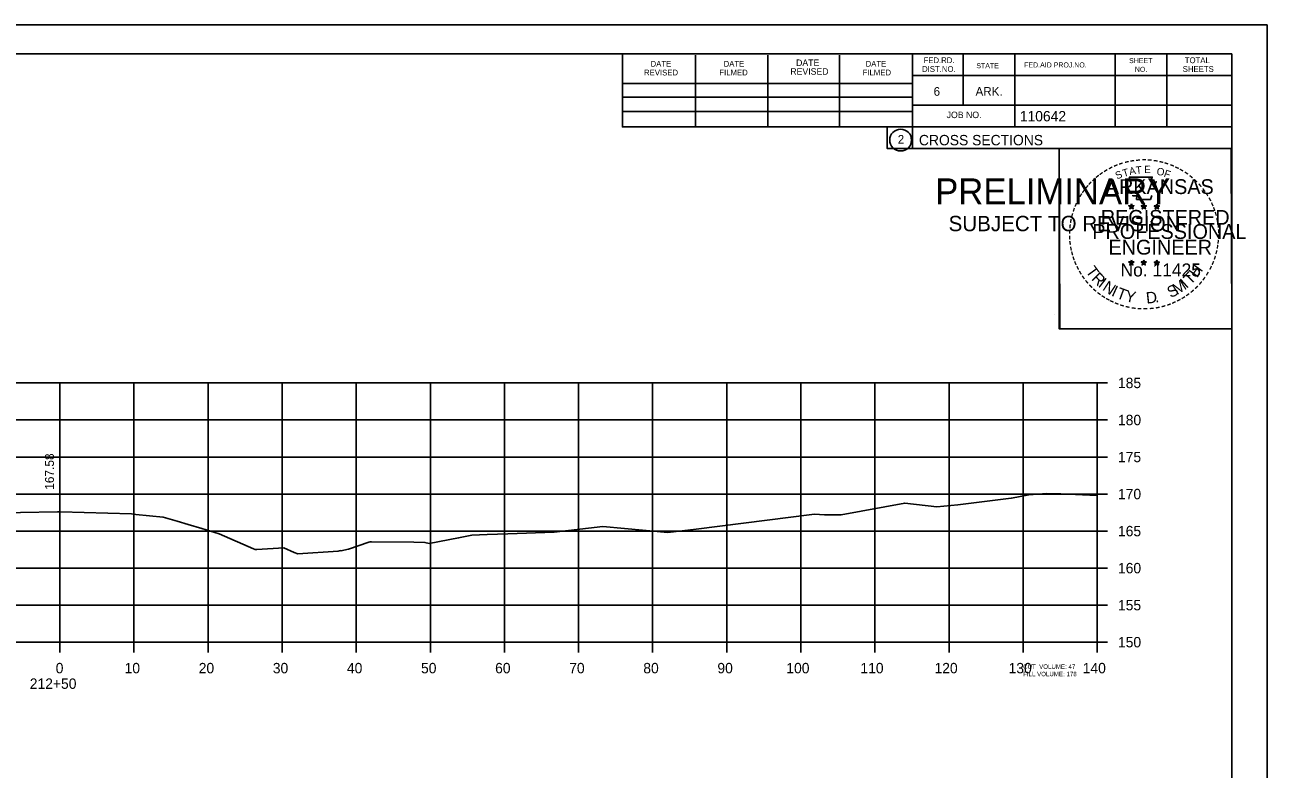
# Model space of a CAD drawing. Extents: x 1368503 to 1373085, y 379840 to 381833.
# Drawn here: x 1368668.3 to 1368836, y 381092.2 to 381192.7 of the extents above; entities that cross this region are included whole.
import ezdxf

# ---------------------------------------------------------------- set-up
doc = ezdxf.new("R2010")
doc.units = 0
for name, color, linetype in [('S_BRIDGE', 7, 'Continuous'), ('S_EDGE_PAVEMENT', 7, 'Continuous'), ('S_LANDSCAPING', 7, 'Continuous'), ('S_MISC_BOUNDARY', 7, 'Continuous'), ('S_MISC_BOUNDARY_ANNOT', 7, 'Continuous'), ('S_PHOTO_CENTERS', 7, 'Continuous'), ('S_PHOTO_NOTES', 7, 'Continuous'), ('S_TRAILS', 7, 'Continuous'), ('S_TRAILS_ANNOT', 7, 'Continuous')]:
    doc.layers.add(name, color=color, linetype=linetype)

msp = doc.modelspace()

# ---------------------------------------------------------------- linework, layer by layer
at = {"layer": 'S_BRIDGE'}
for p, q in [((1368515.06, 381188.84), (1368831.24, 381188.84)), ((1368748.98, 381178.96), (1368748.98, 381188.84)), ((1368758.84, 381178.96), (1368758.84, 381188.64)), ((1368768.6, 381178.96), (1368768.6, 381188.64)), ((1368778.28, 381178.96), (1368778.28, 381188.64)), ((1368788.14, 381188.84), (1368788.14, 381176.04)), ((1368794.98, 381188.84), (1368794.98, 381181.9)), ((1368801.92, 381188.84), (1368801.92, 381178.96)), ((1368815.5, 381188.84), (1368815.5, 381178.96)), ((1368822.44, 381188.84), (1368822.44, 381178.96)), ((1368831.24, 380983.38), (1368831.24, 381188.84)), ((1368748.98, 381184.82), (1368788.14, 381184.82)), ((1368831.24, 381185.9), (1368788.14, 381185.9)), ((1368831.24, 381185.92), (1368831.24, 381185.92)), ((1368748.98, 381182.96), (1368788.14, 381182.96)), ((1368831.24, 381181.9), (1368788.14, 381181.9)), ((1368791.1, 381181.9), (1368831.24, 381181.9)), ((1368748.98, 381178.96), (1368748.98, 381181.02)), ((1368748.98, 381181.02), (1368788.14, 381181.02)), ((1368831.24, 381178.96), (1368748.98, 381178.96)), ((1368788.14, 381176.04), (1368831.24, 381176.04))]:
    msp.add_line(p, q, dxfattribs=at)
msp.add_circle((1368786.53, 381177.18), 1.47, dxfattribs=at)
at = {"layer": 'S_EDGE_PAVEMENT'}
for p, q in [((1368813.06, 381109.38), (1368813.06, 381144.38)), ((1368814.46, 381144.38), (1368813.06, 381144.38)), ((1368814.46, 381139.38), (1368813.06, 381139.38)), ((1368814.46, 381134.38), (1368813.06, 381134.38)), ((1368814.46, 381129.38), (1368813.06, 381129.38)), ((1368814.46, 381124.38), (1368813.06, 381124.38)), ((1368814.46, 381119.38), (1368813.06, 381119.38)), ((1368814.46, 381114.38), (1368813.06, 381114.38)), ((1368533.06, 381109.38), (1368813.06, 381109.38)), ((1368673.06, 381107.98), (1368673.06, 381109.38)), ((1368683.06, 381107.98), (1368683.06, 381109.38)), ((1368693.06, 381107.98), (1368693.06, 381109.38)), ((1368703.06, 381107.98), (1368703.06, 381109.38)), ((1368713.06, 381107.98), (1368713.06, 381109.38)), ((1368723.06, 381107.98), (1368723.06, 381109.38)), ((1368733.06, 381107.98), (1368733.06, 381109.38)), ((1368743.06, 381107.98), (1368743.06, 381109.38)), ((1368753.06, 381107.98), (1368753.06, 381109.38)), ((1368763.06, 381107.98), (1368763.06, 381109.38)), ((1368773.06, 381107.98), (1368773.06, 381109.38)), ((1368783.06, 381107.98), (1368783.06, 381109.38)), ((1368793.06, 381107.98), (1368793.06, 381109.38)), ((1368803.06, 381107.98), (1368803.06, 381109.38)), ((1368813.06, 381107.98), (1368813.06, 381109.38)), ((1368814.46, 381109.38), (1368813.06, 381109.38))]:
    msp.add_line(p, q, dxfattribs=at)
at = {"layer": 'S_LANDSCAPING'}
for p, q in [((1368817.32, 381168.3), (1368817.67, 381168.18)), ((1368817.32, 381168.3), (1368817.58, 381168.25)), ((1368817.32, 381168.3), (1368817.56, 381168.17)), ((1368817.46, 381167.89), (1368817.67, 381168.18)), ((1368817.46, 381167.89), (1368817.58, 381168.13)), ((1368817.46, 381167.89), (1368817.67, 381168.1)), ((1368817.67, 381168.55), (1368817.63, 381168.3)), ((1368817.67, 381168.18), (1368817.67, 381168.55)), ((1368817.67, 381168.55), (1368817.72, 381168.3)), ((1368818.02, 381168.3), (1368817.67, 381168.18)), ((1368817.89, 381167.89), (1368817.67, 381168.18)), ((1368817.89, 381167.89), (1368817.67, 381168.1)), ((1368818.02, 381168.3), (1368817.73, 381168.25)), ((1368817.89, 381167.89), (1368817.75, 381168.18)), ((1368818.02, 381168.3), (1368817.82, 381168.19)), ((1368818.99, 381168.3), (1368819.34, 381168.18)), ((1368818.99, 381168.3), (1368819.25, 381168.25)), ((1368818.99, 381168.3), (1368819.23, 381168.17)), ((1368819.13, 381167.89), (1368819.34, 381168.18)), ((1368819.13, 381167.89), (1368819.25, 381168.13)), ((1368819.13, 381167.89), (1368819.34, 381168.1)), ((1368819.34, 381168.55), (1368819.3, 381168.3)), ((1368819.34, 381168.18), (1368819.34, 381168.55)), ((1368819.34, 381168.55), (1368819.39, 381168.3)), ((1368819.69, 381168.3), (1368819.34, 381168.18)), ((1368819.56, 381167.89), (1368819.34, 381168.18)), ((1368819.56, 381167.89), (1368819.34, 381168.1)), ((1368819.69, 381168.3), (1368819.4, 381168.25)), ((1368819.56, 381167.89), (1368819.42, 381168.18)), ((1368819.69, 381168.3), (1368819.49, 381168.19)), ((1368820.76, 381168.28), (1368821.11, 381168.17)), ((1368820.76, 381168.28), (1368821.01, 381168.24)), ((1368820.76, 381168.28), (1368820.99, 381168.16)), ((1368820.89, 381167.88), (1368821.11, 381168.17)), ((1368820.89, 381167.88), (1368821.02, 381168.12)), ((1368820.89, 381167.88), (1368821.1, 381168.09)), ((1368821.11, 381168.54), (1368821.07, 381168.29)), ((1368821.32, 381167.88), (1368821.1, 381168.09)), ((1368821.11, 381168.17), (1368821.11, 381168.54)), ((1368821.11, 381168.54), (1368821.16, 381168.29)), ((1368821.45, 381168.28), (1368821.11, 381168.17)), ((1368821.32, 381167.88), (1368821.11, 381168.17)), ((1368821.45, 381168.28), (1368821.17, 381168.23)), ((1368821.32, 381167.88), (1368821.18, 381168.17)), ((1368821.45, 381168.28), (1368821.25, 381168.18)), ((1368817.32, 381160.72), (1368817.67, 381160.61)), ((1368817.32, 381160.72), (1368817.57, 381160.68)), ((1368817.32, 381160.72), (1368817.56, 381160.6)), ((1368817.45, 381160.31), (1368817.67, 381160.61)), ((1368817.45, 381160.31), (1368817.58, 381160.56)), ((1368817.45, 381160.31), (1368817.67, 381160.53)), ((1368817.67, 381160.98), (1368817.63, 381160.72)), ((1368817.67, 381160.61), (1368817.67, 381160.98)), ((1368817.67, 381160.98), (1368817.72, 381160.73)), ((1368818.02, 381160.72), (1368817.67, 381160.61)), ((1368817.88, 381160.31), (1368817.67, 381160.61)), ((1368817.88, 381160.31), (1368817.67, 381160.53)), ((1368818.02, 381160.72), (1368817.73, 381160.67)), ((1368817.88, 381160.31), (1368817.74, 381160.61)), ((1368818.02, 381160.72), (1368817.81, 381160.62)), ((1368818.99, 381160.72), (1368819.34, 381160.61)), ((1368818.99, 381160.72), (1368819.24, 381160.68)), ((1368818.99, 381160.72), (1368819.23, 381160.6)), ((1368819.12, 381160.31), (1368819.34, 381160.61)), ((1368819.12, 381160.31), (1368819.25, 381160.56)), ((1368819.12, 381160.31), (1368819.34, 381160.53)), ((1368819.34, 381160.98), (1368819.3, 381160.72)), ((1368819.34, 381160.61), (1368819.34, 381160.98)), ((1368819.34, 381160.98), (1368819.39, 381160.73)), ((1368819.68, 381160.72), (1368819.34, 381160.61)), ((1368819.55, 381160.31), (1368819.34, 381160.61)), ((1368819.55, 381160.31), (1368819.34, 381160.53)), ((1368819.68, 381160.72), (1368819.4, 381160.67)), ((1368819.55, 381160.31), (1368819.41, 381160.61)), ((1368819.68, 381160.72), (1368819.48, 381160.62)), ((1368820.76, 381160.71), (1368821.1, 381160.6)), ((1368820.76, 381160.71), (1368821.01, 381160.67)), ((1368820.76, 381160.71), (1368820.99, 381160.59)), ((1368820.89, 381160.3), (1368821.1, 381160.6)), ((1368820.89, 381160.3), (1368821.01, 381160.55)), ((1368820.89, 381160.3), (1368821.1, 381160.52)), ((1368821.1, 381160.97), (1368821.06, 381160.71)), ((1368821.1, 381160.6), (1368821.1, 381160.97)), ((1368821.1, 381160.97), (1368821.15, 381160.72)), ((1368821.45, 381160.71), (1368821.1, 381160.6)), ((1368821.32, 381160.3), (1368821.1, 381160.6)), ((1368821.32, 381160.3), (1368821.1, 381160.52)), ((1368821.45, 381160.71), (1368821.17, 381160.66)), ((1368821.32, 381160.3), (1368821.18, 381160.6)), ((1368821.45, 381160.71), (1368821.25, 381160.61))]:
    msp.add_line(p, q, dxfattribs=at)
for points in [[(1368817.36, 381172.17), (1368817.63, 381171.35)], [(1368820.88, 381171.25), (1368821.02, 381171.54), (1368820.33, 381171.51), (1368820.48, 381172.17), (1368817.36, 381172.17)], [(1368817.86, 381169.75), (1368817.86, 381169.66), (1368818.42, 381169.64), (1368818.37, 381169.17), (1368820.24, 381169.17), (1368820.44, 381169.71)], [(1368817.67, 381168.55), (1368817.89, 381167.89), (1368817.32, 381168.3), (1368818.02, 381168.3), (1368817.46, 381167.89), (1368817.67, 381168.55)], [(1368819.34, 381168.55), (1368819.56, 381167.89), (1368818.99, 381168.3), (1368819.69, 381168.3), (1368819.13, 381167.89), (1368819.34, 381168.55)], [(1368821.11, 381168.54), (1368821.32, 381167.88), (1368820.76, 381168.28), (1368821.45, 381168.28), (1368820.89, 381167.88), (1368821.11, 381168.54)], [(1368817.67, 381160.98), (1368817.88, 381160.31), (1368817.32, 381160.72), (1368818.02, 381160.72), (1368817.45, 381160.31), (1368817.67, 381160.98)], [(1368819.34, 381160.98), (1368819.55, 381160.31), (1368818.99, 381160.72), (1368819.68, 381160.72), (1368819.12, 381160.31), (1368819.34, 381160.98)], [(1368821.1, 381160.97), (1368821.32, 381160.3), (1368820.76, 381160.71), (1368821.45, 381160.71), (1368820.89, 381160.3), (1368821.1, 381160.97)]]:
    msp.add_lwpolyline(points, dxfattribs=at)
for centre, radius in [((1368817.67, 381168.18), 0.172), ((1368817.67, 381168.18), 0.145), ((1368817.67, 381168.18), 0.116), ((1368817.67, 381168.18), 0.0991), ((1368817.67, 381168.18), 0.0747), ((1368817.67, 381168.18), 0.0495), ((1368817.67, 381168.18), 0.0296), ((1368819.34, 381168.18), 0.172), ((1368819.34, 381168.18), 0.145), ((1368819.34, 381168.18), 0.116), ((1368819.34, 381168.18), 0.0991), ((1368819.34, 381168.18), 0.0747), ((1368819.34, 381168.18), 0.0495), ((1368819.34, 381168.18), 0.0296), ((1368821.11, 381168.17), 0.172), ((1368821.11, 381168.17), 0.145), ((1368821.11, 381168.17), 0.116), ((1368821.11, 381168.17), 0.0991), ((1368821.11, 381168.17), 0.0747), ((1368821.11, 381168.17), 0.0495), ((1368821.11, 381168.17), 0.0296), ((1368817.67, 381160.61), 0.172), ((1368817.67, 381160.61), 0.145), ((1368817.67, 381160.61), 0.116), ((1368817.67, 381160.61), 0.0991), ((1368817.67, 381160.61), 0.0747), ((1368817.67, 381160.61), 0.0495), ((1368817.67, 381160.61), 0.0296), ((1368819.34, 381160.61), 0.172), ((1368819.34, 381160.61), 0.145), ((1368819.34, 381160.61), 0.116), ((1368819.34, 381160.61), 0.0991), ((1368819.34, 381160.61), 0.0747), ((1368819.34, 381160.61), 0.0495), ((1368819.34, 381160.61), 0.0296), ((1368821.1, 381160.6), 0.172), ((1368821.1, 381160.6), 0.145), ((1368821.1, 381160.6), 0.116), ((1368821.1, 381160.6), 0.0991), ((1368821.1, 381160.6), 0.0747), ((1368821.1, 381160.6), 0.0495), ((1368821.1, 381160.6), 0.0296)]:
    msp.add_circle(centre, radius, dxfattribs=at)
at = {"layer": 'S_MISC_BOUNDARY'}
msp.add_lwpolyline([(1368662.7, 381126.81), (1368672.76, 381126.97), (1368673.15, 381126.96), (1368682.74, 381126.69), (1368683.3, 381126.64), (1368687.02, 381126.27), (1368688.9, 381125.7), (1368690.37, 381125.28), (1368692.2, 381124.71), (1368694.56, 381124.01), (1368699.2, 381121.97), (1368699.4, 381121.88), (1368699.66, 381121.89), (1368703.29, 381122.12), (1368704.7, 381121.49), (1368705.19, 381121.29), (1368710.6, 381121.67), (1368710.93, 381121.74), (1368710.99, 381121.7), (1368712.03, 381121.95), (1368714.76, 381122.87), (1368714.93, 381122.93), (1368714.97, 381122.93), (1368715.1, 381122.93), (1368720.82, 381122.89), (1368722.33, 381122.85), (1368722.92, 381122.71), (1368726.88, 381123.45), (1368728.67, 381123.84), (1368730.71, 381123.93), (1368733.5, 381124.02), (1368739.78, 381124.25), (1368746.36, 381125.01), (1368755.09, 381124.18), (1368758.92, 381124.66), (1368774.92, 381126.68), (1368776.26, 381126.59), (1368777, 381126.56), (1368778.48, 381126.57), (1368787.08, 381128.16), (1368791.41, 381127.65), (1368794.23, 381127.93), (1368801.45, 381128.82), (1368801.48, 381128.82), (1368803.82, 381129.26), (1368806.25, 381129.44), (1368808.14, 381129.4), (1368813.06, 381129.18)], dxfattribs=at)
at = {"layer": 'S_PHOTO_CENTERS'}
for p, q in [((1368533.06, 381144.38), (1368813.06, 381144.38)), ((1368673.06, 381109.38), (1368673.06, 381144.38)), ((1368683.06, 381109.38), (1368683.06, 381144.38)), ((1368693.06, 381109.38), (1368693.06, 381144.38)), ((1368703.06, 381109.38), (1368703.06, 381144.38)), ((1368713.06, 381109.38), (1368713.06, 381144.38)), ((1368723.06, 381109.38), (1368723.06, 381144.38)), ((1368733.06, 381109.38), (1368733.06, 381144.38)), ((1368743.06, 381109.38), (1368743.06, 381144.38)), ((1368753.06, 381109.38), (1368753.06, 381144.38)), ((1368763.06, 381109.38), (1368763.06, 381144.38)), ((1368773.06, 381109.38), (1368773.06, 381144.38)), ((1368783.06, 381109.38), (1368783.06, 381144.38)), ((1368793.06, 381109.38), (1368793.06, 381144.38)), ((1368803.06, 381109.38), (1368803.06, 381144.38)), ((1368813.06, 381109.38), (1368813.06, 381144.38)), ((1368533.06, 381139.38), (1368813.06, 381139.38)), ((1368533.06, 381134.38), (1368813.06, 381134.38)), ((1368533.06, 381129.38), (1368813.06, 381129.38)), ((1368533.06, 381124.38), (1368813.06, 381124.38)), ((1368533.06, 381119.38), (1368813.06, 381119.38)), ((1368533.06, 381114.38), (1368813.06, 381114.38)), ((1368533.06, 381109.38), (1368813.06, 381109.38))]:
    msp.add_line(p, q, dxfattribs=at)
at = {"layer": 'S_PHOTO_NOTES'}
for p, q in [((1368502.66, 381192.73), (1368835.99, 381192.73)), ((1368807.27, 381153.58), (1368807.27, 381153.58))]:
    msp.add_line(p, q, dxfattribs=at)
for points in [[(1368502.65, 381192.73), (1368835.99, 381192.73), (1368835.99, 380979.4), (1368502.65, 380979.4)], [(1368748.98, 381188.84), (1368748.98, 381178.96), (1368784.71, 381178.96), (1368784.71, 381176.04), (1368807.91, 381176.04), (1368807.91, 381151.71), (1368831.24, 381151.71), (1368831.24, 380983.38), (1368515.06, 380983.38), (1368515.06, 381188.84)], [(1368807.91, 381176.04), (1368831.12, 381176.04), (1368831.24, 381151.71), (1368808.03, 381151.71)]]:
    msp.add_lwpolyline(points, close=True, dxfattribs=at)

# ---------------------------------------------------------------- texts
at = {"layer": 'S_BRIDGE'}
for s, height, p in [('DATE', 0.879, (1368772.42, 381187.18)), ('FED.RD.', 0.782, (1368789.62, 381187.56)), ('SHEET', 0.684, (1368817.36, 381187.56)), ('TOTAL', 0.782, (1368824.88, 381187.56)), ('REVISED', 0.782, (1368751.9, 381185.9)), ('DATE', 0.782, (1368752.78, 381187.08)), ('FILMED', 0.782, (1368762.06, 381185.9)), ('DATE', 0.782, (1368762.64, 381187.08)), ('REVISED', 0.879, (1368771.64, 381186)), ('FILMED', 0.782, (1368781.4, 381185.9)), ('DATE', 0.782, (1368781.8, 381187.08)), ('DIST.NO.', 0.782, (1368789.42, 381186.38)), ('STATE', 0.684, (1368796.74, 381186.88)), ('FED.AID PROJ.NO.', 0.684, (1368803.2, 381186.98)), ('NO.', 0.684, (1368818.14, 381186.38)), ('SHEETS', 0.782, (1368824.6, 381186.38)), ('6', 1.17, (1368790.98, 381183.16)), ('ARK.', 1.172, (1368796.64, 381183.16)), ('JOB NO.', 0.879, (1368792.74, 381180.14)), ('110642', 1.4, (1368802.61, 381179.7)), ('2', 1.17, (1368786.14, 381176.69)), ('CROSS SECTIONS', 1.4, (1368789, 381176.47))]:
    msp.add_text(s, height=height, rotation=360, dxfattribs=at).set_placement(p)
at = {"layer": 'S_LANDSCAPING'}
for s, height, rotation, p in [('-', 1.6, 5.8968, (1368818.27, 381173.81)), ('-', 1.6, 0.1862, (1368819.04, 381173.89)), ('-', 1.6, 357.743, (1368819.76, 381173.87)), ('-', 1.6, 36.2317, (1368813.67, 381171.95)), ('-', 1.6, 34.0636, (1368814.25, 381172.34)), ('-', 1.6, 28.7918, (1368814.85, 381172.71)), ('-', 1.6, 24.3072, (1368815.48, 381173.03)), ('S', 1, 21.594, (1368815.72, 381171.85)), ('-', 1.6, 19.1761, (1368816.11, 381173.3)), ('T', 1, 16.4036, (1368816.63, 381172.18)), ('-', 1.6, 13.6301, (1368816.86, 381173.54)), ('A', 1, 11.2132, (1368817.46, 381172.43)), ('-', 1.6, 10.2193, (1368817.54, 381173.7)), ('T', 1, 6.0228, (1368818.31, 381172.6)), ('E', 1, 0.8323, (1368819.41, 381172.71)), ('-', 1.6, 352.1617, (1368820.51, 381173.82)), ('O', 1, 350.4515, (1368821.02, 381172.5)), ('-', 1.6, 347.2049, (1368821.23, 381173.7)), ('F', 1, 340.0707, (1368821.97, 381172.27)), ('-', 1.6, 342.3362, (1368821.86, 381173.55)), ('-', 1.6, 337.8551, (1368822.6, 381173.32)), ('-', 1.6, 334.1211, (1368823.23, 381173.05)), ('-', 1.6, 329.6409, (1368823.81, 381172.77)), ('-', 1.6, 325.8627, (1368824.45, 381172.41)), ('-', 1.6, 48.423, (1368812.31, 381170.68)), ('-', 1.6, 42.9622, (1368812.76, 381171.15)), ('-', 1.6, 38.9507, (1368813.19, 381171.57)), ('ARKANSAS', 2, 360, (1368814.22, 381169.89)), ('-', 1.6, 320.5297, (1368825.06, 381171.98)), ('-', 1.6, 315.5786, (1368825.66, 381171.5)), ('-', 1.6, 309.8797, (1368826.23, 381170.95)), ('-', 1.6, 58.0706, (1368811.17, 381169.1)), ('-', 1.6, 54.2325, (1368811.5, 381169.62)), ('-', 1.6, 50.6142, (1368811.91, 381170.19)), ('-', 1.6, 306.6522, (1368826.75, 381170.34)), ('-', 1.4, 303.6753, (1368827.24, 381169.78)), ('-', 1.6, 72.3945, (1368810.38, 381167.24)), ('-', 1.6, 67.7743, (1368810.6, 381167.87)), ('-', 1.6, 62.8713, (1368810.86, 381168.48)), ('DWB', 0.01, 360, (1368817.66, 381168.18)), ('DWB', 0.01, 360, (1368819.33, 381168.18)), ('DWB', 0.01, 360, (1368821.09, 381168.17)), ('-', 1.6, 299.6684, (1368827.56, 381169.17)), ('-', 1.6, 294.6628, (1368827.88, 381168.56)), ('-', 1.6, 290.5728, (1368828.14, 381167.98)), ('-', 1.6, 81.2013, (1368810.05, 381165.81)), ('-', 1.6, 75.461, (1368810.18, 381166.53)), ('REGISTERED', 2, 360, (1368813.54, 381165.74)), ('-', 1.6, 285.1233, (1368828.37, 381167.4)), ('-', 1.6, 280.5493, (1368828.57, 381166.66)), ('-', 1.6, 89.0622, (1368809.95, 381164.42)), ('-', 1.6, 85.1863, (1368809.98, 381165.12)), ('PROFESSIONAL', 2, 360, (1368812.39, 381163.83)), ('-', 1.6, 276.5962, (1368828.74, 381165.89)), ('-', 1.6, 274.3301, (1368828.8, 381165.17)), ('-', 1.6, 94.1959, (1368809.99, 381163.7)), ('-', 1.6, 98.9479, (1368810.06, 381163.03)), ('ENGINEER', 2, 360, (1368814.58, 381161.71)), ('-', 1.6, 260.9953, (1368828.74, 381163.22)), ('-', 1.6, 263.5172, (1368828.81, 381163.87)), ('-', 1.6, 269.9407, (1368828.83, 381164.54)), ('-', 1.6, 101.7149, (1368810.19, 381162.3)), ('-', 1.6, 105.4578, (1368810.36, 381161.7)), ('-', 1.6, 109.0874, (1368810.57, 381161.07)), ('-', 1.6, 252.8681, (1368828.45, 381161.82)), ('-', 1.6, 255.7626, (1368828.63, 381162.54)), ('-', 1.6, 114.0643, (1368810.82, 381160.48)), ('-', 1.6, 115.7289, (1368811.13, 381159.86)), ('-', 1.6, 120.4471, (1368811.49, 381159.27)), ('T', 1.54, 306.0406, (1368811.43, 381159.45)), ('No. 11425', 1.757, 360, (1368816.21, 381158.76)), ('DWB', 0.01, 360, (1368817.66, 381160.61)), ('DWB', 0.01, 360, (1368819.33, 381160.61)), ('DWB', 0.01, 360, (1368821.09, 381160.6)), ('T', 1.54, 46.6444, (1368825.66, 381157.54)), ('H', 1.54, 54.6088, (1368826.55, 381158.48)), ('-', 1.6, 244.6197, (1368827.96, 381160.52)), ('-', 1.6, 247.8887, (1368828.23, 381161.14)), ('-', 1.6, 125.8934, (1368811.89, 381158.71)), ('-', 1.6, 130.7181, (1368812.35, 381158.16)), ('R', 1.54, 314.005, (1368812.19, 381158.4)), ('I', 1.54, 321.9694, (1368813.09, 381157.47)), ('N', 1.54, 326.5002, (1368813.66, 381157)), ('M', 1.54, 32.6563, (1368823.81, 381156.22)), ('I', 1.54, 42.1136, (1368825.1, 381157.06)), ('-', 1.6, 231.2538, (1368826.74, 381158.54)), ('-', 1.6, 233.8452, (1368827.17, 381159.11)), ('-', 1.6, 239.0712, (1368827.57, 381159.76)), ('-', 1.6, 134.2238, (1368812.87, 381157.61)), ('-', 1.6, 138.9338, (1368813.39, 381157.15)), ('-', 1.6, 144.6463, (1368813.95, 381156.74)), ('-', 1.6, 148.0898, (1368814.51, 381156.37)), ('I', 1.54, 335.3603, (1368814.87, 381156.21)), ('T', 1.54, 339.8912, (1368815.53, 381155.88)), ('Y', 1.54, 347.8556, (1368816.74, 381155.44)), ('D', 1.54, 6.3969, (1368819.73, 381155.08)), ('S', 1.54, 26.9312, (1368822.97, 381155.81)), ('-', 1.6, 212.2491, (1368824.65, 381156.61)), ('-', 1.6, 215.7363, (1368825.19, 381157)), ('-', 1.6, 221.0851, (1368825.74, 381157.47)), ('-', 1.6, 225.7653, (1368826.26, 381157.98)), ('-', 1.6, 151.5704, (1368815.09, 381156.05)), ('-', 1.6, 154.6002, (1368815.61, 381155.8)), ('-', 1.6, 158.5612, (1368816.24, 381155.55)), ('-', 1.6, 162.7983, (1368816.92, 381155.33)), ('-', 1.6, 167.5555, (1368817.64, 381155.17)), ('-', 1.6, 173.1155, (1368818.41, 381155.06)), ('-', 1.6, 176.5183, (1368819.16, 381155.01)), ('-', 1.6, 181.5918, (1368819.9, 381155.03)), ('-', 1.6, 185.8167, (1368820.71, 381155.1)), ('-', 1.6, 191.2858, (1368821.45, 381155.23)), ('.', 1.54, 13.7642, (1368820.92, 381155.21)), ('-', 1.6, 195.4743, (1368822.18, 381155.43)), ('-', 1.6, 200.7184, (1368822.85, 381155.67)), ('-', 1.6, 204.2516, (1368823.47, 381155.95)), ('-', 1.6, 207.3568, (1368824.1, 381156.27))]:
    msp.add_text(s, height=height, rotation=rotation, dxfattribs=at).set_placement(p)
at = {"layer": 'S_MISC_BOUNDARY_ANNOT'}
for s, height, p in [('PRELIMINARY', 3.5, (1368791.19, 381168.5)), ('DWB', 0.01, (1368791.94, 381170.35)), ('SUBJECT TO REVISION', 2.0751, (1368793, 381164.87))]:
    msp.add_text(s, height=height, rotation=360, dxfattribs=at).set_placement(p)
at = {"layer": 'S_TRAILS'}
for s, height, p in [('185', 1.4, (1368815.86, 381143.68)), ('180', 1.4, (1368815.86, 381138.68)), ('175', 1.4, (1368815.86, 381133.68)), ('170', 1.4, (1368815.86, 381128.68)), ('165', 1.4, (1368815.86, 381123.68)), ('160', 1.4, (1368815.86, 381118.68)), ('155', 1.4, (1368815.86, 381113.68)), ('150', 1.4, (1368815.86, 381108.68)), ('0', 1.4, (1368672.5, 381105.18)), ('10', 1.4, (1368681.8, 381105.18)), ('20', 1.4, (1368691.8, 381105.18)), ('30', 1.4, (1368701.8, 381105.18)), ('40', 1.4, (1368711.8, 381105.18)), ('50', 1.4, (1368721.8, 381105.18)), ('60', 1.4, (1368731.8, 381105.18)), ('70', 1.4, (1368741.8, 381105.18)), ('80', 1.4, (1368751.8, 381105.18)), ('90', 1.4, (1368761.8, 381105.18)), ('100', 1.4, (1368771.1, 381105.18)), ('110', 1.4, (1368781.1, 381105.18)), ('120', 1.4, (1368791.1, 381105.18)), ('130', 1.4, (1368801.1, 381105.18)), ('CUT  VOLUME: 47', 0.6, (1368803.06, 381105.78)), ('140', 1.4, (1368811.1, 381105.18)), ('212+50', 1.4, (1368669, 381103.08)), ('FILL VOLUME: 178', 0.6, (1368803.06, 381104.78))]:
    msp.add_text(s, height=height, dxfattribs=at).set_placement(p)
at = {"layer": 'S_TRAILS_ANNOT'}
msp.add_text('167.58', height=1.2, rotation=90, dxfattribs=at).set_placement((1368672.26, 381129.96))

doc.saveas('drawing.dxf')
